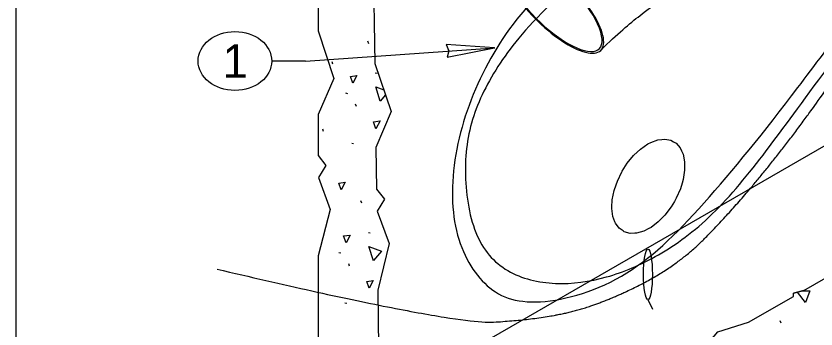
# Model space of a CAD drawing. Extents: x 99862 to 103151, y 100000 to 105076.
# Drawn here: x 99862 to 100242.3, y 101382.8 to 101531.8 of the extents above; entities that cross this region are included whole.
import ezdxf

# ---------------------------------------------------------------- set-up
doc = ezdxf.new("R2010")
doc.units = 0
for name, color, linetype in [('Level 1', 7, 'Continuous'), ('Level 11', 7, 'Continuous'), ('Level 12', 7, 'Continuous'), ('Level 15', 7, 'Continuous'), ('Level 19', 7, 'Continuous'), ('Level 20', 7, 'Continuous')]:
    doc.layers.add(name, color=color, linetype=linetype)

msp = doc.modelspace()

# ---------------------------------------------------------------- linework, layer by layer
at = {"layer": 'Level 1'}
for p, q in [((100035.62, 101348.4), (100591.77, 101669.5)), ((100037.1, 101444.6), (100033.65, 101438.92)), ((100033.65, 101438.92), (100039.45, 101423.45)), ((100039.45, 101423.45), (100033.97, 101401.34)), ((100033.97, 101401.34), (100034.63, 101352.82))]:
    msp.add_line(p, q, dxfattribs=at)
msp.add_lwpolyline([(99862, 99999.5), (103151, 99999.5), (103151, 102075.5), (99862, 102075.5)], close=True, dxfattribs=at)
for points in [[(100014.33, 101666.89), (100005.63, 101661.86), (100012.23, 101649.39), (100005.63, 101631.92), (100005.63, 101602.63), (100009.54, 101585.3), (100005.63, 101572.78), (100005.63, 101524.75), (100013.12, 101502.09), (100005.63, 101484.97), (100005.63, 101465.33), (100009.32, 101460.64), (100005.82, 101454.99), (100011.37, 101439.67), (100005.63, 101417.7), (100005.63, 101369.56), (100008.98, 101353.53)], [(100231.49, 101398.32), (100231.61, 101399.87), (100236.4, 101401.15), (100256.25, 101412.62), (100261.81, 101421.69), (100288.76, 101431.39), (100335.41, 101458.32), (100339.24, 101462.27), (100346.23, 101471.6), (100369.88, 101478.22), (100394.77, 101492.59), (100419.5, 101514.35), (100442.97, 101520.42), (100480.19, 101541.91), (100493.71, 101554.05), (100503.87, 101555.58), (100526.01, 101568.36), (100533.53, 101578.18), (100564.44, 101590.55), (100591.77, 101606.33), (100597.09, 101612.95), (100616.11, 101620.38)], [(100031.8, 101595.87), (100031.43, 101587.74), (100035.61, 101570.25), (100031.84, 101557.65), (100032.5, 101509.24), (100040.36, 101486.36), (100033.05, 101469.14), (100033.32, 101449.35), (100037.1, 101444.6)], [(100145.24, 101440.14), (100145.27, 101440.74), (100145.43, 101444.29), (100146.31, 101448.71), (100146.47, 101449.2), (100147.83, 101453.2), (100149.93, 101457.6), (100150.12, 101457.9), (100152.54, 101461.72), (100155.55, 101465.4), (100155.67, 101465.51), (100158.84, 101468.5), (100162.28, 101470.89), (100163.72, 101471.65), (100167.13, 101472.88), (100168.9, 101473.07), (100170.36, 101473.22), (100173.28, 101472.67), (100174.55, 101471.95), (100175.77, 101471.25), (100175.77, 101471.25)], [(100149.93, 101457.6), (100150.12, 101457.9), (100152.54, 101461.72), (100155.55, 101465.4), (100155.67, 101465.51), (100158.84, 101468.5), (100162.28, 101470.89), (100163.72, 101471.65), (100167.13, 101472.88), (100168.9, 101473.07), (100170.36, 101473.22), (100173.28, 101472.67), (100174.55, 101471.95), (100175.77, 101471.25), (100177.73, 101469.01), (100178.37, 101467.6), (100179.09, 101466.03), (100179.79, 101462.45), (100179.79, 101460.68), (100179.8, 101458.4), (100179.12, 101454.04), (100178.59, 101452.24), (100177.79, 101449.55), (100175.84, 101445.11), (100174.94, 101443.57), (100173.37, 101440.89), (100170.47, 101437.07), (100169.41, 101435.99), (100167.25, 101433.78), (100163.84, 101431.18), (100162.83, 101430.64), (100160.38, 101429.35), (100157.01, 101428.37), (100156.2, 101428.35), (100153.86, 101428.29), (100151.05, 101429.1), (100150.54, 101429.46), (100148.71, 101430.77), (100146.92, 101433.24), (100146.7, 101433.81), (100145.74, 101436.4), (100145.24, 101440.14), (100145.27, 101440.74), (100145.43, 101444.29), (100146.31, 101448.71), (100146.47, 101449.2), (100147.83, 101453.2), (100149.93, 101457.6)], [(100175.77, 101471.25), (100177.73, 101469.01), (100178.37, 101467.6), (100179.09, 101466.03), (100179.79, 101462.45), (100179.79, 101460.68), (100179.8, 101458.4), (100179.12, 101454.04), (100178.59, 101452.24), (100177.79, 101449.55), (100175.84, 101445.11), (100174.94, 101443.57), (100173.37, 101440.89), (100170.47, 101437.07), (100169.41, 101435.99), (100167.25, 101433.78), (100163.84, 101431.18), (100162.83, 101430.64), (100160.38, 101429.35), (100157.01, 101428.37), (100156.2, 101428.35), (100153.86, 101428.29), (100151.05, 101429.1)], [(100151.05, 101429.1), (100151.05, 101429.1), (100150.54, 101429.46), (100148.71, 101430.77), (100146.92, 101433.24), (100146.7, 101433.81), (100145.74, 101436.4), (100145.24, 101440.14)], [(100091.89, 101319.74), (100095.28, 101319.68), (100109.37, 101327.82), (100110.94, 101330.71), (100115.55, 101331.38), (100137.09, 101343.82), (100144.44, 101351.08), (100151.95, 101352.4), (100189.48, 101374.07), (100195.53, 101381.4), (100210.11, 101385.98), (100231.49, 101398.32), (100231.49, 101398.32)], [(100236.4, 101401.15), (100231.61, 101399.87), (100231.61, 101399.87)]]:
    msp.add_lwpolyline(points, dxfattribs=at)
at = {"layer": 'Level 11'}
msp.add_line((100162.38, 101396.78), (100164.57, 101392.29), dxfattribs=at)
msp.add_ellipse((100162.38, 101408.81), major_axis=(0, -12.02), ratio=0.175836, dxfattribs=at)
for points, degree in [([(100120.19, 101551.11), (100105.55, 101538.21), (100087.44, 101515.4), (100070.2, 101473.73), (100067.63, 101431.82), (100082.22, 101402.72), (100105.17, 101391.83), (100151.49, 101404.13), (100187.44, 101439.3), (100232.93, 101495.51), (100282.7, 101565.12), (100358.1, 101650.97), (100419.76, 101707.79), (100437.7, 101722.9), (100449.7, 101732.31)], 3), ([(100125.3, 101546.25), (100108.46, 101530.57), (100093.03, 101512.76), (100078.44, 101485.99), (100074.06, 101458.79), (100078.8, 101426.3), (100094.3, 101408.58), (100118.39, 101403), (100142.62, 101406.4), (100167.19, 101416.82), (100192.92, 101435.31), (100218.95, 101467.37), (100243.11, 101501.4), (100299.23, 101574.55), (100312.63, 101589.26), (100338.12, 101621.3), (100368.87, 101655.61), (100410.79, 101695.5), (100445.97, 101725.32), (100452.4, 101729.21)], 3), ([(99957.6, 101411.25), (100069.25, 101384.96), (100109.14, 101387.22), (100138.37, 101393.78), (100175.62, 101412.21), (100201.69, 101438.21), (100232.24, 101475.5), (100267.64, 101526.24), (100342.25, 101616.04), (100396.35, 101671.77), (100432, 101706.94), (100453.65, 101727.38)], 2)]:
    msp.add_open_spline(points, degree=degree, dxfattribs=at)
at = {"layer": 'Level 12'}
for p, q in [((100029.63, 101518.64), (100029.19, 101519.78)), ((100012.67, 101508.88), (100012.23, 101510.03)), ((100032.73, 101504.79), (100033.61, 101504.61)), ((100018.65, 101495.18), (100019.53, 101495.01)), ((100037.65, 101494.26), (100035.16, 101491.31)), ((100023.78, 101488.72), (100023.34, 101489.87)), ((100008.23, 101476.85), (100007.79, 101477.99)), ((100021.58, 101471.23), (100022.46, 101471.05)), ((100026.42, 101442.66), (100025.98, 101443.8)), ((100029.52, 101428.81), (100030.4, 101428.63)), ((100015.44, 101419.2), (100016.32, 101419.03)), ((100020.57, 101412.74), (100020.13, 101413.89)), ((100237.23, 101395.35), (100233.44, 101400.36)), ((100018.37, 101395.25), (100019.25, 101395.07)), ((100225.63, 101385.56), (100225.19, 101386.71))]:
    msp.add_line(p, q, dxfattribs=at)
for points in [[(100022.07, 101499.83), (100020.93, 101503.08), (100024.01, 101503.52), (100022.07, 101499.83)], [(100035.07, 101491.22), (100032.96, 101498.08), (100036.84, 101496.6)], [(100033.1, 101478.18), (100031.96, 101481.43), (100035.03, 101481.87), (100033.1, 101478.18)], [(100016.54, 101449.05), (100015.4, 101452.3), (100018.48, 101452.74), (100016.54, 101449.05)], [(100018.86, 101423.85), (100017.71, 101427.1), (100020.79, 101427.54), (100018.86, 101423.85)], [(100031.86, 101415.24), (100029.75, 101422.1), (100035.72, 101419.81), (100031.94, 101415.33)], [(100029.88, 101402.19), (100028.74, 101405.45), (100031.82, 101405.89), (100029.88, 101402.19)], [(100235.91, 101401.02), (100239.31, 101400.97), (100237.29, 101395.46)]]:
    msp.add_lwpolyline(points, dxfattribs=at)
at = {"layer": 'Level 15'}
for q in [(100089.57, 101516.7), (99983.56, 101510.4)]:
    msp.add_line((99999.56, 101510.4), q, dxfattribs=at)
msp.add_lwpolyline([(100089.48, 101516.61), (100066.51, 101518.19), (100067.75, 101515.28), (100066.87, 101512.23)], close=True, dxfattribs=at)
at = {"layer": 'Level 19'}
for major_axis, start_param, end_param in [((22.33, -22.66), 2.408367, 8.345746), ((23.05, -23.39), 3.141588, 6.283206), ((23.05, -23.39), 0.00002, 2.068016)]:
    msp.add_ellipse((100116.86, 101538.87), major_axis=major_axis, ratio=0.351881, start_param=start_param, end_param=end_param, dxfattribs=at)
msp.add_open_spline([(100139.91, 101515.48), (100148.13, 101523.59), (100158.67, 101532.55), (100169.14, 101539.8), (100171.68, 101541.5)], degree=3, dxfattribs=at)
at = {"layer": 'Level 20'}
msp.add_ellipse((99966.06, 101510.4), major_axis=(-17.5, 0), ratio=0.8, dxfattribs=at)

# ---------------------------------------------------------------- texts
msp.add_text('1', height=16, dxfattribs=at).set_placement((99960.26, 101502.4))

doc.saveas('drawing.dxf')
